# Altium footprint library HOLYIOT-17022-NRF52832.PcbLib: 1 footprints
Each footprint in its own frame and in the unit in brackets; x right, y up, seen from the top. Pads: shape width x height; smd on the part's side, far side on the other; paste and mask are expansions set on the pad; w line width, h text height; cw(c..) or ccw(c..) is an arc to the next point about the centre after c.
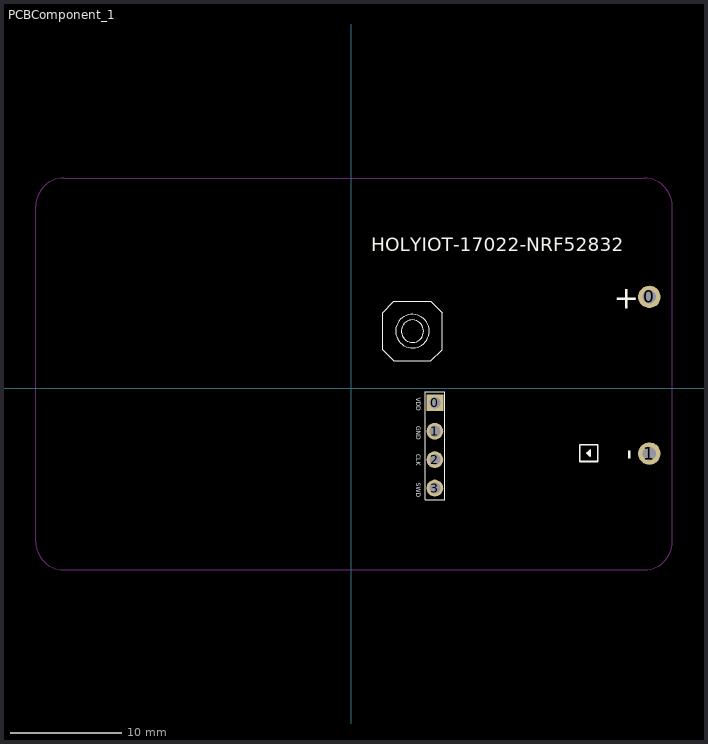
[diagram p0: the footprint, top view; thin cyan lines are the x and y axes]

## PCBComponent_1 [mm]
pads (6):
  rect 1.5x1.5 hole 1: 0(7.457,-1.29)
  round 2 hole 1.2: 0(26.617,8.17) 1(26.617,-5.83)
  round 1.5 hole 1: 1(7.457,-3.83) 2(7.457,-6.37) 3(7.457,-8.91)
Top Overlay:
  circle w0.1: c5.447,5.11 r1
  circle w0.1: c5.447,5.11 r1.5
  region: 21.327,-5.505 21.047,-5.785 21.327,-6.065
  lines w0.1: 2.797,3.46 3.797,2.46 7.097,2.46 8.097,3.46 8.097,6.76 7.097,7.76 3.797,7.76 2.797,6.76 2.797,3.46 ; 6.607,-9.95 8.317,-9.95 8.317,-0.31 6.607,-0.31 6.607,-9.95
  lines w0.15: 20.407,-6.54 20.407,-5.04 ; 22.007,-6.54 22.007,-5.04
  lines w0.152: 20.407,-6.54 22.007,-6.54 ; 20.407,-5.04 22.007,-5.04 ; 21.047,-5.785 21.327,-6.065 21.327,-5.505 21.047,-5.785
  text "GND" at 5.797,-3.38 h0.4
  text "VDD" at 5.797,-0.85 h0.4
  text "SWD" at 5.797,-8.44 h0.4
  text "CLK" at 5.797,-5.91 h0.4
  text "HOLYIOT-17022-NRF52832" at 1.777,12.26 h1.2
  text "+" at 23.43,7.09 h2
  text "-" at 25.58,-6.42 h2
Bottom Overlay:
  lines w0.1: -27.873,-14.73 -27.873,17.29 28.327,17.29 28.327,-14.73 -27.873,-14.73
Keep-Out Layer:
  lines w0.1: -28.193,-13.72 ccw(c-25.693,-13.72) -25.693,-16.22 26.157,-16.22 ccw(c26.157,-13.72) 28.657,-13.72 28.657,16.28 ccw(c26.157,16.28) 26.157,18.78 -25.693,18.78 ccw(c-25.693,16.28) -28.193,16.28 -28.193,-13.72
